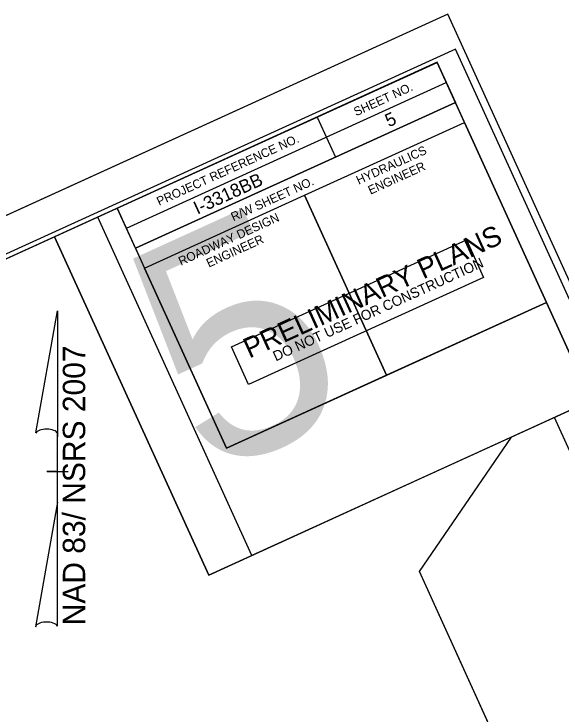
# Model space of a CAD drawing. Extents: x 2247864 to 2249896, y 662531 to 664296.
# Drawn here: x 2249194.5 to 2249505.8, y 663827.6 to 664225.8 of the extents above; entities that cross this region are included whole.
import ezdxf

# ---------------------------------------------------------------- set-up
doc = ezdxf.new("R2010")
doc.units = 0
for name, color, linetype in [('Matchline', 7, 'Continuous'), ('Prop North Arrow NAD83 for Plan Sheets CELL', 7, 'Continuous'), ('Sheet Clip Boundary CELL', 7, 'Continuous'), ('Sheet Cutting Line CELL', 7, 'Continuous'), ('Sheet Data Field CELL', 7, 'Continuous'), ('Sheet Layout Plan Border', 7, 'Continuous'), ('Sheet Plan CELL', 7, 'Continuous'), ('Sheet Plan Layout CELL', 7, 'Continuous'), ('Sheet Plot Border Inside CELL', 7, 'Continuous'), ('Sheet Plot Border Outside CELL', 7, 'Continuous'), ('Sheet Sticker Preliminary CELL', 7, 'Continuous')]:
    doc.layers.add(name, color=color, linetype=linetype)

msp = doc.modelspace()

# ---------------------------------------------------------------- linework, layer by layer
at = {"layer": 'Matchline'}
msp.add_line((2249677.43, 663353.62), (2249425.27, 663908.72), dxfattribs=at)
at = {"layer": 'Prop North Arrow NAD83 for Plan Sheets CELL'}
for p, q in [((2249206.85, 663987.49), (2249219.15, 664057.02)), ((2249219.22, 664057.02), (2249219.15, 664057.02)), ((2249219.22, 664057.02), (2249219.15, 664057.02)), ((2249219.22, 664057.02), (2249219.22, 663985.32)), ((2249219.22, 663948.12), (2249219.22, 663987.42)), ((2249219.22, 663985.32), (2249219.22, 663987.34)), ((2249213.22, 663965.52), (2249213.15, 663965.52)), ((2249218.55, 663965.52), (2249213.22, 663965.52)), ((2249213.3, 663965.52), (2249225.3, 663965.52)), ((2249219.22, 663948.12), (2249206.7, 663877.24)), ((2249219.3, 663877.54), (2249219.22, 663948.12))]:
    msp.add_line(p, q, dxfattribs=at)
for centre, start_param, end_param in [((2249213.05, 663986.75), 0.216388, 2.908219), ((2249213.05, 663877), 0.201328, 3.141593)]:
    msp.add_ellipse(centre, major_axis=(6.35, -0.05), ratio=0.461098, start_param=start_param, end_param=end_param, dxfattribs=at)
at = {"layer": 'Sheet Clip Boundary CELL'}
msp.add_lwpolyline([(2248241.67, 663371.06), (2248514.44, 662770.57), (2248551.22, 662641.58), (2249564.56, 663103.35), (2249531.17, 663176.64), (2249788.88, 663294.08), (2249780.68, 663312.06), (2249743.43, 663294.89), (2249677.44, 663353.62), (2249425.27, 663908.72), (2249477.5, 663985.14), (2249305.27, 663906.66), (2249217.58, 664099.11), (2248115.83, 663597.06)], close=True, dxfattribs=at)
at = {"layer": 'Sheet Cutting Line CELL'}
msp.add_line((2249441.45, 664225.83), (2247909.5, 663527.75), dxfattribs=at)
at = {"layer": 'Sheet Layout Plan Border'}
msp.add_lwpolyline([(2248198.13, 663481.51), (2248575.77, 662652.77), (2249849.75, 663233.3), (2249502.05, 663996.33), (2249329.83, 663917.85), (2249242.13, 664110.3), (2248140.38, 663608.25)], close=True, dxfattribs=at)
at = {"layer": 'Sheet Plan CELL'}
for p, q in [((2249258.45, 664103.96), (2249440.49, 664186.9)), ((2249263.66, 664092.55), (2249445.68, 664175.52)), ((2249263.66, 664092.55), (2249445.68, 664175.52)), ((2249367.05, 664167.15), (2249377.46, 664144.42)), ((2249359.88, 664122.68), (2249406.53, 664020.34)), ((2249263.66, 664092.55), (2249268.84, 664081.19))]:
    msp.add_line(p, q, dxfattribs=at)
for points in [[(2249435.32, 664198.33), (2248070.33, 663576.33), (2248505.72, 662620.85), (2249870.7, 663242.85)], [(2249253.26, 664115.38), (2249435.32, 664198.33), (2249445.68, 664175.52), (2249263.66, 664092.55)], [(2249359.88, 664122.68), (2249450.86, 664164.15), (2249497.53, 664061.77), (2249406.53, 664020.29)], [(2249268.84, 664081.19), (2249359.88, 664122.68), (2249406.53, 664020.29), (2249315.49, 663978.83)], [(2248505.72, 662620.85), (2248070.31, 663576.29), (2249253.26, 664115.38), (2249315.49, 663978.83), (2249497.53, 664061.77), (2249870.7, 663242.85)]]:
    msp.add_lwpolyline(points, close=True, dxfattribs=at)
at = {"layer": 'Sheet Plan Layout CELL'}
for points in [[(2249305.27, 663906.66), (2249523.01, 664005.88), (2249435.34, 664198.34), (2249217.58, 664099.11)], [(2248070.31, 663576.29), (2248505.72, 662620.85), (2249870.68, 663242.84), (2249522.99, 664005.87), (2249305.27, 663906.66), (2249217.58, 664099.11)]]:
    msp.add_lwpolyline(points, close=True, dxfattribs=at)
at = {"layer": 'Sheet Plot Border Inside CELL'}
msp.add_lwpolyline([(2248367.09, 662554.92), (2249883.1, 663245.75), (2249445.65, 664205.77), (2247929.62, 663514.94)], close=True, dxfattribs=at)
at = {"layer": 'Sheet Plot Border Outside CELL'}
msp.add_lwpolyline([(2248363.56, 662531.33), (2249895.5, 663229.41), (2249441.45, 664225.83), (2247909.5, 663527.75)], close=True, dxfattribs=at)
at = {"layer": 'Sheet Sticker Preliminary CELL'}
msp.add_lwpolyline([(2249327.91, 664015.07), (2249318.17, 664036.46), (2249451.94, 664097.41), (2249461.68, 664076.03)], close=True, dxfattribs=at)

# ---------------------------------------------------------------- texts
at = {"layer": 'Prop North Arrow NAD83 for Plan Sheets CELL'}
msp.add_text('NAD 83/ NSRS 2007', height=12.75, rotation=90, dxfattribs=at).set_placement((2249235, 663878.07))
at = {"layer": 'Sheet Data Field CELL'}
for s, p in [('5', (2249407.76, 664161.32)), ('I-3318BB', (2249298.8, 664111.6))]:
    msp.add_text(s, height=7.5, rotation=24.4979, dxfattribs=at).set_placement(p)
at = {"layer": 'Sheet Plan CELL'}
for s, height, p in [('SHEET NO.', 5, (2249389.2, 664167.62)), ('PROJECT REFERENCE NO.', 5.0001, (2249277.08, 664116.65)), ('HYDRAULICS', 5, (2249390.62, 664128.69)), ('ENGINEER', 5, (2249397.34, 664123)), ('R/W SHEET NO.', 5.0001, (2249319.34, 664107.83)), ('ROADWAY DESIGN', 5.0001, (2249289.49, 664082.58)), ('ENGINEER', 5, (2249305.35, 664081.52))]:
    msp.add_text(s, height=height, rotation=24.4979, dxfattribs=at).set_placement(p)
at = {"layer": 'Sheet Plan Layout CELL'}
msp.add_text('5 ', height=131.25, rotation=24.4979, dxfattribs=at).set_placement((2249303.42, 663961.22))
at = {"layer": 'Sheet Sticker Preliminary CELL'}
for s, height, p in [('PRELIMINARY PLANS', 11.52, (2249328.38, 664029.73)), ('DO NOT USE FOR CONSTRUCTION', 5.76, (2249343.49, 664028.16))]:
    msp.add_text(s, height=height, rotation=24.4979, dxfattribs=at).set_placement(p)

doc.saveas('drawing.dxf')
